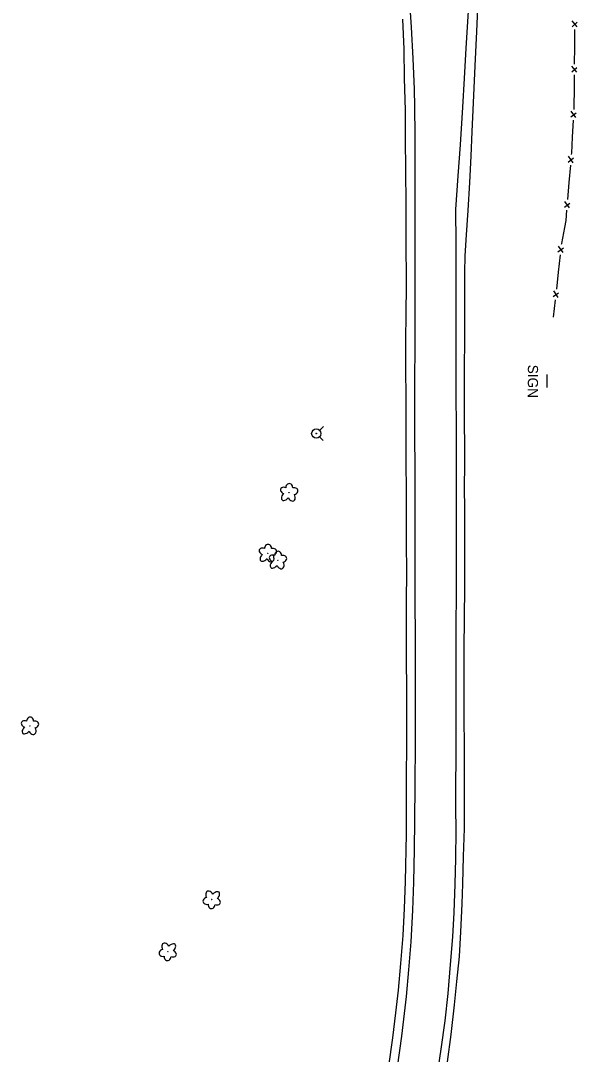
# Model space of a CAD drawing. Extents: x 588843 to 2552415, y 180129 to 269402.
# Drawn here: x 594515 to 594844, y 183376 to 183986 of the extents above; entities that cross this region are included whole.
import ezdxf

# ---------------------------------------------------------------- set-up
doc = ezdxf.new("R2010")
doc.units = 0
for name, color, linetype in [('Default', 7, 'Continuous'), ('E_FEN_P', 7, 'Continuous'), ('E_LAND_Vegetation', 7, 'Continuous'), ('E_RDWY', 7, 'Continuous'), ('E_RDWY_Gravel', 7, 'Continuous'), ('E_SGN', 7, 'Continuous'), ('E_SGN_Text', 7, 'Continuous'), ('E_UTL_WHydrant', 7, 'Continuous')]:
    doc.layers.add(name, color=color, linetype=linetype)

# ---------------------------------------------------------------- blocks, each defined once
blk = doc.blocks.new('HYD')
at = {"layer": 'Default'}
for p, q in [((-3.8, 3.8), (-8.3, 8.3)), ((3.8, 3.8), (8.3, 8.3))]:
    blk.add_line(p, q, dxfattribs=at)
for radius in [5.48, 0.42]:
    blk.add_circle((0, 0), radius, dxfattribs=at)
blk = doc.blocks.new('DTRE')
at = {"layer": 'Default'}
blk.add_circle((-0.2, 0), 0.183, dxfattribs=at)
for centre, major_axis, ratio in [((-5.9, 0.2), (4.93, -0.12), 0.832022), ((-1.9, 5.3), (1.36, -4.98), 0.782863), ((4.1, 2.7), (-5.27, -2.93), 0.691916), ((-2.5, -5.2), (1.8, 4.86), 0.716896), ((3.5, -3.7), (-5.01, 4.58), 0.560249)]:
    blk.add_ellipse(centre, major_axis=major_axis, ratio=ratio, start_param=1.570796, end_param=4.712389, dxfattribs=at)
blk = doc.blocks.new('SIGN')
at = {"layer": 'Default'}
blk.add_text('SIGN', height=12, dxfattribs=at).set_placement((-18.5, -6))

msp = doc.modelspace()

# ---------------------------------------------------------------- linework, layer by layer
at = {"layer": 'E_FEN_P'}
for p, q in [((594843.71, 183981.78), (594840.63, 183985.33)), ((594840.63, 183981.95), (594843.66, 183984.61)), ((594840.43, 183955.28), (594843.48, 183957.92)), ((594843.52, 183955.09), (594840.46, 183958.66)), ((594842.93, 183928.36), (594840.04, 183932.07)), ((594839.86, 183928.69), (594843.02, 183931.19)), ((594838.29, 183902.11), (594841.53, 183904.52)), ((594841.36, 183901.69), (594838.58, 183905.48)), ((594836.07, 183875.52), (594839.31, 183877.93)), ((594839.13, 183875.11), (594836.35, 183878.9)), ((594835.35, 183848.69), (594832.66, 183852.55)), ((594832.3, 183849.19), (594835.59, 183851.51)), ((594829.4, 183822.67), (594832.69, 183824.99)), ((594832.45, 183822.17), (594829.76, 183826.03))]:
    msp.add_line(p, q, dxfattribs=at)
for points in [[(594842.21, 183970.03), (594842.28, 183979.58), (594842.29, 183980.21)], [(594842.13, 183959.84), (594842.21, 183970.03)], [(594842, 183943.35), (594842.08, 183953.54)], [(594841.76, 183933.17), (594841.95, 183936.83), (594842, 183943.35)], [(594840.89, 183916.7), (594841.43, 183926.87)], [(594840.33, 183906.53), (594840.4, 183907.31), (594840.89, 183916.7)], [(594838.96, 183890.1), (594839.81, 183900.25)], [(594838.11, 183879.95), (594838.96, 183890.1)], [(594836.31, 183863.57), (594837.07, 183867.62), (594837.58, 183873.66)], [(594834.45, 183853.56), (594834.49, 183854), (594836.31, 183863.57)], [(594832.65, 183837.16), (594833.76, 183847.29)], [(594831.55, 183827.04), (594832.65, 183837.16)], [(594829.75, 183810.64), (594830.86, 183820.77)]]:
    msp.add_lwpolyline(points, dxfattribs=at)
at = {"layer": 'E_RDWY'}
for points in [[(594747.27, 183477.28), (594747.62, 183496.47), (594747.82, 183513.5), (594748.06, 183534.27), (594748.23, 183559.36), (594748.28, 183583.77), (594748.16, 183602.83), (594748.16, 183622.2), (594748.14, 183642.89), (594748.05, 183664.3), (594748.02, 183683.72), (594748, 183704.54), (594747.99, 183723.21), (594747.91, 183738.8), (594747.9, 183754.08), (594747.94, 183772.82), (594748, 183793.69), (594748, 183813.37), (594748.04, 183834.35), (594748.08, 183853.53), (594748.1, 183882.07), (594748.1, 183899.86), (594747.98, 183918.01), (594747.78, 183934.66), (594747.57, 183945.15), (594746.92, 183963.21), (594745.84, 183981.63), (594744.56, 184002.38)], [(594771.57, 183476.03), (594771.95, 183491.13), (594772.17, 183507.62), (594772.1, 183521.26), (594772.12, 183529.81), (594772.18, 183555.18), (594772.18, 183576.91), (594772.33, 183600.96), (594772.31, 183626.54), (594772.4, 183649.33), (594772.39, 183668.65), (594772.44, 183685.99), (594772.39, 183706.48), (594772.36, 183726.29), (594772.35, 183745.19), (594772.3, 183765.26), (594772.26, 183788.51), (594772.2, 183810.52), (594772.26, 183830.82), (594772.19, 183854.3), (594772.14, 183874.06), (594773.46, 183893.88), (594774.71, 183912.17), (594776.13, 183934.48), (594777.16, 183951.48), (594778.22, 183969.38), (594779.54, 183991.22)], [(594737.67, 183367.96), (594740.27, 183386.24), (594742.98, 183409.69), (594744.4, 183425.57), (594745.76, 183441.99), (594746.74, 183460.71), (594747.27, 183477.28)], [(594761.12, 183362.77), (594763.42, 183378.71), (594765.69, 183395.33), (594767.53, 183411.44), (594768.99, 183428.65), (594770.29, 183444.93), (594770.97, 183459.21), (594771.57, 183476.09)]]:
    msp.add_lwpolyline(points, dxfattribs=at)
at = {"layer": 'E_RDWY_Gravel'}
for points in [[(594776.16, 183476.14), (594776.66, 183492.37), (594777.06, 183508.94), (594777.17, 183529.71), (594777.13, 183553.01), (594776.99, 183578.47), (594776.97, 183596.69), (594777.02, 183614.43), (594777.21, 183633.15), (594777.42, 183651.09), (594777.41, 183668.08), (594777.36, 183684.18), (594777.33, 183696.95), (594777.23, 183710.49), (594777.35, 183723.31), (594777.41, 183734.62), (594777.18, 183748.19), (594777.18, 183766.48), (594777.21, 183781.73), (594777.3, 183796.3), (594777.42, 183813.83), (594777.42, 183824.84), (594777.41, 183837.01), (594777.63, 183846.84), (594778.36, 183859.08), (594779.28, 183873.52), (594780.28, 183890.11), (594781.03, 183905.56), (594781.77, 183920.07), (594782.38, 183936.97), (594783.36, 183958.77), (594784.35, 183979.21), (594785.18, 183997.3)], [(594742.28, 183477.67), (594742.86, 183505.58), (594742.86, 183523.68), (594743.01, 183540.82), (594743.1, 183556.84), (594743.15, 183576.68), (594743.11, 183591.83), (594743.02, 183607.86), (594742.9, 183624.61), (594742.93, 183642.35), (594743.09, 183660.65), (594742.91, 183676.76), (594742.91, 183694.44), (594742.91, 183710.21), (594742.83, 183722.95), (594742.74, 183741.62), (594742.65, 183763.5), (594742.5, 183779.64), (594742.6, 183796.7), (594742.66, 183812.81), (594742.85, 183829.09), (594742.71, 183857.32), (594742.73, 183877.02), (594742.63, 183897.43), (594742.35, 183915.68), (594742.29, 183932.72), (594741.81, 183951.42), (594741.5, 183968.7), (594740.74, 183986.39)], [(594732.43, 183368.63), (594734.88, 183385.36), (594736.72, 183400.1), (594738.17, 183413.38), (594739.54, 183429.28), (594740.9, 183445.68), (594741.7, 183461.68), (594742.28, 183477.67)], [(594767.11, 183371.13), (594769.36, 183387.23), (594771.35, 183404.81), (594772.7, 183418.64), (594774.12, 183433.31), (594775.08, 183447.94), (594775.84, 183464.43), (594776.16, 183476.14)]]:
    msp.add_lwpolyline(points, dxfattribs=at)
at = {"layer": 'E_SGN'}
msp.add_lwpolyline([(594825.88, 183769.17), (594825.97, 183776.78)], dxfattribs=at)

# ---------------------------------------------------------------- block references
at = {"layer": 'E_LAND_Vegetation'}
for p, xscale, yscale, rotation in [((594673.68, 183706.95), 0.4999999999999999, 0.5, -90.21750690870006), ((594661.12, 183671.11), 0.4999999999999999, 0.5, -90.21750690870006), ((594667.06, 183667.01), 0.4999999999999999, 0.5, -90.21750690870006), ((594520.76, 183569.24), 0.4999999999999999, 0.5, -90.21750690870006), ((594628.1, 183467.06), 0.5, 0.5000000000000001, 88.58947073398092), ((594602.16, 183436.34), 0.5, 0.5000000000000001, 88.58947073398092)]:
    msp.add_blockref('DTRE', p, dxfattribs=dict(at, xscale=xscale, yscale=yscale, rotation=rotation))
at = {"layer": 'E_SGN_Text', "xscale": 0.4999999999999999, "yscale": 0.5, "rotation": -90.21750690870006}
msp.add_blockref('SIGN', (594817.52, 183773.25), dxfattribs=at)
at = {"layer": 'E_UTL_WHydrant', "xscale": 0.4999999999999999, "yscale": 0.5, "rotation": -90.21750690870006}
msp.add_blockref('HYD', (594689.73, 183741.89), dxfattribs=at)

doc.saveas('drawing.dxf')
